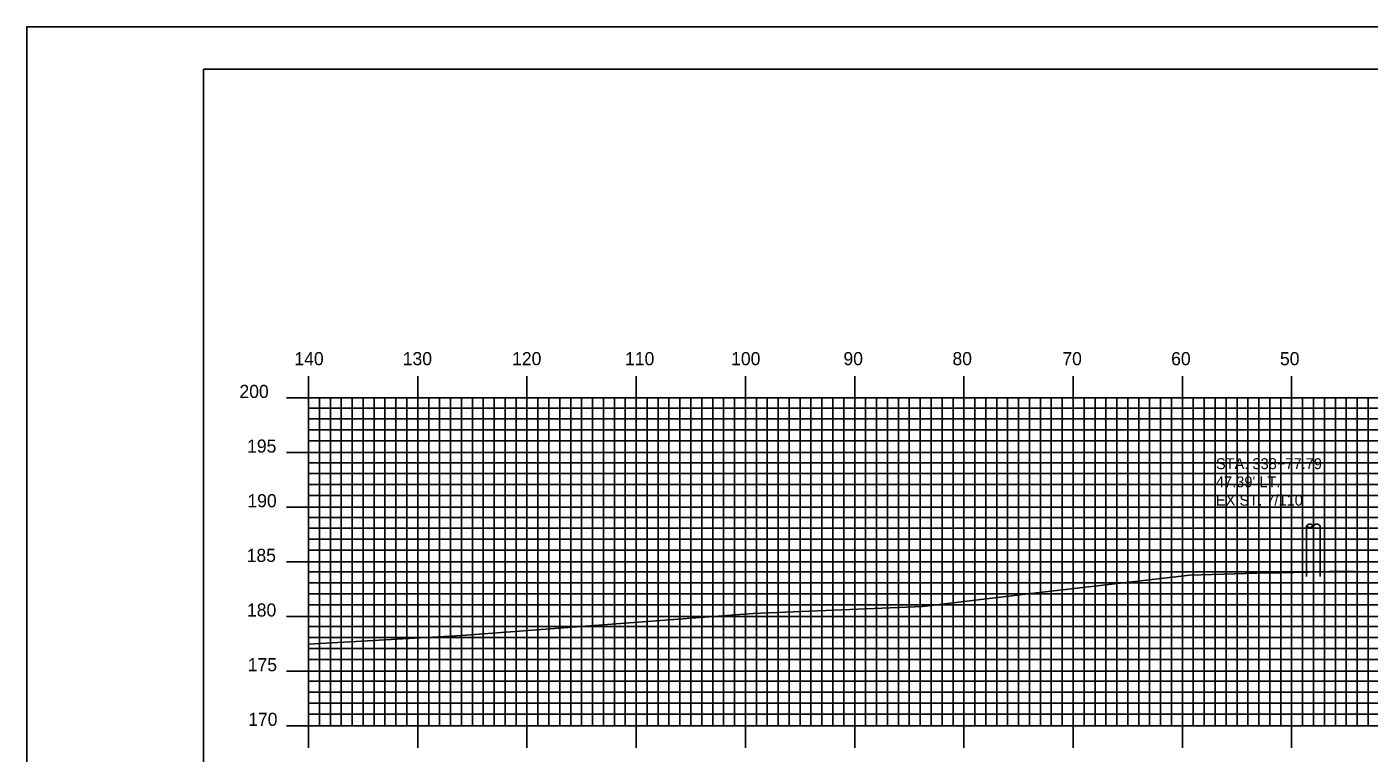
# Model space of a CAD drawing. Extents: x 1823966 to 1824309, y 442591 to 442811.
# Drawn here: x 1823966 to 1824088.9, y 442744.1 to 442810.5 of the extents above; entities that cross this region are included whole.
import ezdxf

# ---------------------------------------------------------------- set-up
doc = ezdxf.new("R2010")
doc.units = 0
for name, color, linetype in [('BORDER', 7, 'Continuous'), ('D_Text_Monospaced', 7, 'Continuous'), ('H_V ANNOTATION', 7, 'Continuous'), ('MAJOR', 7, 'Continuous'), ('MINOR', 7, 'Continuous'), ('PLOT BOUNDARY', 7, 'Continuous'), ('S_Roadway_Centerline', 7, 'Continuous'), ('S_Utilities_Pole_Power', 7, 'Continuous')]:
    doc.layers.add(name, color=color, linetype=linetype)

msp = doc.modelspace()

# ---------------------------------------------------------------- linework, layer by layer
at = {"layer": 'BORDER'}
msp.add_lwpolyline([(1823982.22, 442596.67), (1824302.22, 442596.67), (1824302.22, 442806.67), (1823982.22, 442806.67)], close=True, dxfattribs=at)
at = {"layer": 'MAJOR'}
for p, q in [((1823991.82, 442778.59), (1823991.82, 442776.59)), ((1824001.82, 442778.59), (1824001.82, 442776.59)), ((1824011.82, 442778.59), (1824011.82, 442776.59)), ((1824021.82, 442778.59), (1824021.82, 442776.59)), ((1824031.82, 442778.59), (1824031.82, 442776.59)), ((1824041.82, 442778.59), (1824041.82, 442776.59)), ((1824051.82, 442778.59), (1824051.82, 442776.59)), ((1824061.82, 442778.59), (1824061.82, 442776.59)), ((1824071.82, 442778.59), (1824071.82, 442776.59)), ((1824081.82, 442778.59), (1824081.82, 442776.59)), ((1823989.82, 442776.59), (1823991.82, 442776.59)), ((1823991.82, 442776.59), (1824271.82, 442776.59)), ((1823991.82, 442746.59), (1823991.82, 442776.59)), ((1823991.82, 442746.59), (1823991.82, 442776.59)), ((1824001.82, 442746.59), (1824001.82, 442776.59)), ((1824011.82, 442746.59), (1824011.82, 442776.59)), ((1824021.82, 442746.59), (1824021.82, 442776.59)), ((1824031.82, 442746.59), (1824031.82, 442776.59)), ((1824041.82, 442746.59), (1824041.82, 442776.59)), ((1824051.82, 442746.59), (1824051.82, 442776.59)), ((1824061.82, 442746.59), (1824061.82, 442776.59)), ((1824071.82, 442746.59), (1824071.82, 442776.59)), ((1824081.82, 442746.59), (1824081.82, 442776.59)), ((1823989.82, 442771.59), (1823991.82, 442771.59)), ((1823991.82, 442771.59), (1824271.82, 442771.59)), ((1823989.82, 442766.59), (1823991.82, 442766.59)), ((1823991.82, 442766.59), (1824271.82, 442766.59)), ((1823989.82, 442761.59), (1823991.82, 442761.59)), ((1823991.82, 442761.59), (1824271.82, 442761.59)), ((1823989.82, 442756.59), (1823991.82, 442756.59)), ((1823991.82, 442756.59), (1824271.82, 442756.59)), ((1823989.82, 442751.59), (1823991.82, 442751.59)), ((1823991.82, 442751.59), (1824271.82, 442751.59)), ((1823989.82, 442746.59), (1823991.82, 442746.59)), ((1823991.82, 442746.59), (1824271.82, 442746.59)), ((1823991.82, 442746.59), (1824271.82, 442746.59)), ((1823991.82, 442744.58), (1823991.82, 442746.59)), ((1824001.82, 442744.58), (1824001.82, 442746.59)), ((1824011.82, 442744.58), (1824011.82, 442746.59)), ((1824021.82, 442744.58), (1824021.82, 442746.59)), ((1824031.82, 442744.58), (1824031.82, 442746.59)), ((1824041.82, 442744.58), (1824041.82, 442746.59)), ((1824051.82, 442744.58), (1824051.82, 442746.59)), ((1824061.82, 442744.58), (1824061.82, 442746.59)), ((1824071.82, 442744.58), (1824071.82, 442746.59)), ((1824081.82, 442744.58), (1824081.82, 442746.59))]:
    msp.add_line(p, q, dxfattribs=at)
at = {"layer": 'MINOR'}
for p, q in [((1823992.82, 442746.59), (1823992.82, 442776.59)), ((1823993.82, 442746.59), (1823993.82, 442776.59)), ((1823994.82, 442746.59), (1823994.82, 442776.59)), ((1823995.82, 442746.59), (1823995.82, 442776.59)), ((1823996.82, 442746.59), (1823996.82, 442776.59)), ((1823997.82, 442746.59), (1823997.82, 442776.59)), ((1823998.82, 442746.59), (1823998.82, 442776.59)), ((1823999.82, 442746.59), (1823999.82, 442776.59)), ((1824000.82, 442746.59), (1824000.82, 442776.59)), ((1824002.82, 442746.59), (1824002.82, 442776.59)), ((1824003.82, 442746.59), (1824003.82, 442776.59)), ((1824004.82, 442746.59), (1824004.82, 442776.59)), ((1824005.82, 442746.59), (1824005.82, 442776.59)), ((1824006.82, 442746.59), (1824006.82, 442776.59)), ((1824007.82, 442746.59), (1824007.82, 442776.59)), ((1824008.82, 442746.59), (1824008.82, 442776.59)), ((1824009.82, 442746.59), (1824009.82, 442776.59)), ((1824010.82, 442746.59), (1824010.82, 442776.59)), ((1824012.82, 442746.59), (1824012.82, 442776.59)), ((1824013.82, 442746.59), (1824013.82, 442776.59)), ((1824014.82, 442746.59), (1824014.82, 442776.59)), ((1824015.82, 442746.59), (1824015.82, 442776.59)), ((1824016.82, 442746.59), (1824016.82, 442776.59)), ((1824017.82, 442746.59), (1824017.82, 442776.59)), ((1824018.82, 442746.59), (1824018.82, 442776.59)), ((1824019.82, 442746.59), (1824019.82, 442776.59)), ((1824020.82, 442746.59), (1824020.82, 442776.59)), ((1824022.82, 442746.59), (1824022.82, 442776.59)), ((1824023.82, 442746.59), (1824023.82, 442776.59)), ((1824024.82, 442746.59), (1824024.82, 442776.59)), ((1824025.82, 442746.59), (1824025.82, 442776.59)), ((1824026.82, 442746.59), (1824026.82, 442776.59)), ((1824027.82, 442746.59), (1824027.82, 442776.59)), ((1824028.82, 442746.59), (1824028.82, 442776.59)), ((1824029.82, 442746.59), (1824029.82, 442776.59)), ((1824030.82, 442746.59), (1824030.82, 442776.59)), ((1824032.82, 442746.59), (1824032.82, 442776.59)), ((1824033.82, 442746.59), (1824033.82, 442776.59)), ((1824034.82, 442746.59), (1824034.82, 442776.59)), ((1824035.82, 442746.59), (1824035.82, 442776.59)), ((1824036.82, 442746.59), (1824036.82, 442776.59)), ((1824037.82, 442746.59), (1824037.82, 442776.59)), ((1824038.82, 442746.59), (1824038.82, 442776.59)), ((1824039.82, 442746.59), (1824039.82, 442776.59)), ((1824040.82, 442746.59), (1824040.82, 442776.59)), ((1824042.82, 442746.59), (1824042.82, 442776.59)), ((1824043.82, 442746.59), (1824043.82, 442776.59)), ((1824044.82, 442746.59), (1824044.82, 442776.59)), ((1824045.82, 442746.59), (1824045.82, 442776.59)), ((1824046.82, 442746.59), (1824046.82, 442776.59)), ((1824047.82, 442746.59), (1824047.82, 442776.59)), ((1824048.82, 442746.59), (1824048.82, 442776.59)), ((1824049.82, 442746.59), (1824049.82, 442776.59)), ((1824050.82, 442746.59), (1824050.82, 442776.59)), ((1824052.82, 442746.59), (1824052.82, 442776.59)), ((1824053.82, 442746.59), (1824053.82, 442776.59)), ((1824054.82, 442746.59), (1824054.82, 442776.59)), ((1824055.82, 442746.59), (1824055.82, 442776.59)), ((1824056.82, 442746.59), (1824056.82, 442776.59)), ((1824057.82, 442746.59), (1824057.82, 442776.59)), ((1824058.82, 442746.59), (1824058.82, 442776.59)), ((1824059.82, 442746.59), (1824059.82, 442776.59)), ((1824060.82, 442746.59), (1824060.82, 442776.59)), ((1824062.82, 442746.59), (1824062.82, 442776.59)), ((1824063.82, 442746.59), (1824063.82, 442776.59)), ((1824064.82, 442746.59), (1824064.82, 442776.59)), ((1824065.82, 442746.59), (1824065.82, 442776.59)), ((1824066.82, 442746.59), (1824066.82, 442776.59)), ((1824067.82, 442746.59), (1824067.82, 442776.59)), ((1824068.82, 442746.59), (1824068.82, 442776.59)), ((1824069.82, 442746.59), (1824069.82, 442776.59)), ((1824070.82, 442746.59), (1824070.82, 442776.59)), ((1824072.82, 442746.59), (1824072.82, 442776.59)), ((1824073.82, 442746.59), (1824073.82, 442776.59)), ((1824074.82, 442746.59), (1824074.82, 442776.59)), ((1824075.82, 442746.59), (1824075.82, 442776.59)), ((1824076.82, 442746.59), (1824076.82, 442776.59)), ((1824077.82, 442746.59), (1824077.82, 442776.59)), ((1824078.82, 442746.59), (1824078.82, 442776.59)), ((1824079.82, 442746.59), (1824079.82, 442776.59)), ((1824080.82, 442746.59), (1824080.82, 442776.59)), ((1824082.82, 442746.59), (1824082.82, 442776.59)), ((1824083.82, 442746.59), (1824083.82, 442776.59)), ((1824084.82, 442746.59), (1824084.82, 442776.59)), ((1824085.82, 442746.59), (1824085.82, 442776.59)), ((1824086.82, 442746.59), (1824086.82, 442776.59)), ((1824087.82, 442746.59), (1824087.82, 442776.59)), ((1824088.82, 442746.59), (1824088.82, 442776.59)), ((1823991.82, 442775.67), (1824271.82, 442775.67)), ((1823991.82, 442775.67), (1823993.83, 442775.67)), ((1823991.82, 442775.67), (1823993.83, 442775.67)), ((1823991.82, 442774.67), (1824271.82, 442774.67)), ((1823991.82, 442774.67), (1823993.83, 442774.67)), ((1823991.82, 442773.67), (1824271.82, 442773.67)), ((1823991.82, 442772.67), (1824271.82, 442772.67)), ((1823991.82, 442772.67), (1823993.83, 442772.67)), ((1823991.82, 442770.67), (1824271.82, 442770.67)), ((1823991.82, 442770.67), (1823993.83, 442770.67)), ((1823991.82, 442769.67), (1824271.82, 442769.67)), ((1823991.82, 442769.67), (1823993.83, 442769.67)), ((1823991.82, 442768.67), (1824271.82, 442768.67)), ((1823991.82, 442767.67), (1824271.82, 442767.67)), ((1823991.82, 442767.67), (1823993.83, 442767.67)), ((1823991.82, 442765.67), (1824271.82, 442765.67)), ((1823991.82, 442765.67), (1823993.83, 442765.67)), ((1823991.82, 442764.67), (1824271.82, 442764.67)), ((1823991.82, 442764.67), (1823993.83, 442764.67)), ((1823991.82, 442763.67), (1824271.82, 442763.67)), ((1823991.82, 442762.67), (1824271.82, 442762.67)), ((1823991.82, 442762.67), (1823993.83, 442762.67)), ((1823991.82, 442760.67), (1824271.82, 442760.67)), ((1823991.82, 442760.67), (1823993.83, 442760.67)), ((1823991.82, 442759.67), (1824271.82, 442759.67)), ((1823991.82, 442759.67), (1823993.83, 442759.67)), ((1823991.82, 442758.67), (1824271.82, 442758.67)), ((1823991.82, 442757.67), (1824271.82, 442757.67)), ((1823991.82, 442757.67), (1823993.83, 442757.67)), ((1823991.82, 442755.67), (1824271.82, 442755.67)), ((1823991.82, 442755.67), (1823993.83, 442755.67)), ((1823991.82, 442754.67), (1824271.82, 442754.67)), ((1823991.82, 442754.67), (1823993.83, 442754.67)), ((1823991.82, 442753.67), (1824271.82, 442753.67)), ((1823991.82, 442752.67), (1824271.82, 442752.67)), ((1823991.82, 442752.67), (1823993.83, 442752.67)), ((1823991.82, 442750.67), (1824271.82, 442750.67)), ((1823991.82, 442750.67), (1823993.83, 442750.67)), ((1823991.82, 442749.67), (1823993.83, 442749.67)), ((1823991.82, 442749.67), (1824271.82, 442749.67)), ((1823991.82, 442748.67), (1824271.82, 442748.67)), ((1823991.82, 442747.67), (1824271.82, 442747.67))]:
    msp.add_line(p, q, dxfattribs=at)
at = {"layer": 'PLOT BOUNDARY'}
msp.add_lwpolyline([(1823966.04, 442590.55), (1824306.04, 442590.55), (1824306.04, 442810.55), (1823966.04, 442810.55)], close=True, dxfattribs=at)
at = {"layer": 'S_Roadway_Centerline'}
msp.add_lwpolyline([(1823991.82, 442754.06), (1824005.87, 442754.86), (1824032.53, 442756.87), (1824048.02, 442757.5), (1824058.45, 442758.77), (1824072.5, 442760.39), (1824078.64, 442760.56), (1824078.93, 442760.59), (1824079.42, 442760.57), (1824084.72, 442760.69), (1824085.88, 442760.73), (1824091.03, 442760.65)], dxfattribs=at)
at = {"layer": 'S_Utilities_Pole_Power'}
for p, q in [((1824083.18, 442764.89), (1824083.33, 442765)), ((1824083.18, 442760.27), (1824083.18, 442764.89)), ((1824083.33, 442764.78), (1824083.18, 442764.89)), ((1824083.65, 442765), (1824083.8, 442764.89)), ((1824083.8, 442764.89), (1824083.65, 442764.78)), ((1824083.96, 442765), (1824083.8, 442764.89)), ((1824084.43, 442764.89), (1824084.27, 442765)), ((1824084.43, 442760.27), (1824084.43, 442764.89))]:
    msp.add_line(p, q, dxfattribs=at)
for centre, start, end in [((1824083.49, 442764.78), 90, 125.2644), ((1824083.49, 442764.78), 54.7356, 90), ((1824084.12, 442764.78), 90, 125.2644), ((1824084.12, 442764.78), 54.7356, 90), ((1824083.49, 442765), 234.7356, 270), ((1824083.49, 442765), 270, 305.2644)]:
    msp.add_arc(centre, 0.271, start, end, dxfattribs=at)

# ---------------------------------------------------------------- texts
at = {"layer": 'D_Text_Monospaced'}
for s, p in [('STA. 338+77.79', (1824074.89, 442770.08)), ("47.39' LT.", (1824074.89, 442768.42)), ('EXIST. 7/110', (1824074.89, 442766.74))]:
    msp.add_text(s, height=1, dxfattribs=at).set_placement(p)
at = {"layer": 'H_V ANNOTATION'}
for s, p in [('140', (1823990.53, 442779.59)), ('130', (1824000.45, 442779.59)), ('120', (1824010.46, 442779.59)), ('110', (1824020.8, 442779.59)), ('100', (1824030.51, 442779.59)), ('90', (1824040.79, 442779.59)), ('80', (1824050.77, 442779.59)), ('70', (1824060.83, 442779.59)), ('60', (1824070.79, 442779.59)), ('50', (1824080.75, 442779.59)), ('200', (1823985.5, 442776.59)), ('195', (1823986.2, 442771.59)), ('190', (1823986.23, 442766.59)), ('185', (1823986.16, 442761.59)), ('180', (1823986.19, 442756.59)), ('175', (1823986.26, 442751.59)), ('170', (1823986.3, 442746.59))]:
    msp.add_text(s, height=1.2, dxfattribs=at).set_placement(p)
at = {"layer": 'MAJOR'}
msp.add_text('-', height=0.012, dxfattribs=at).set_placement((1823991.81, 442746.59))

doc.saveas('drawing.dxf')
